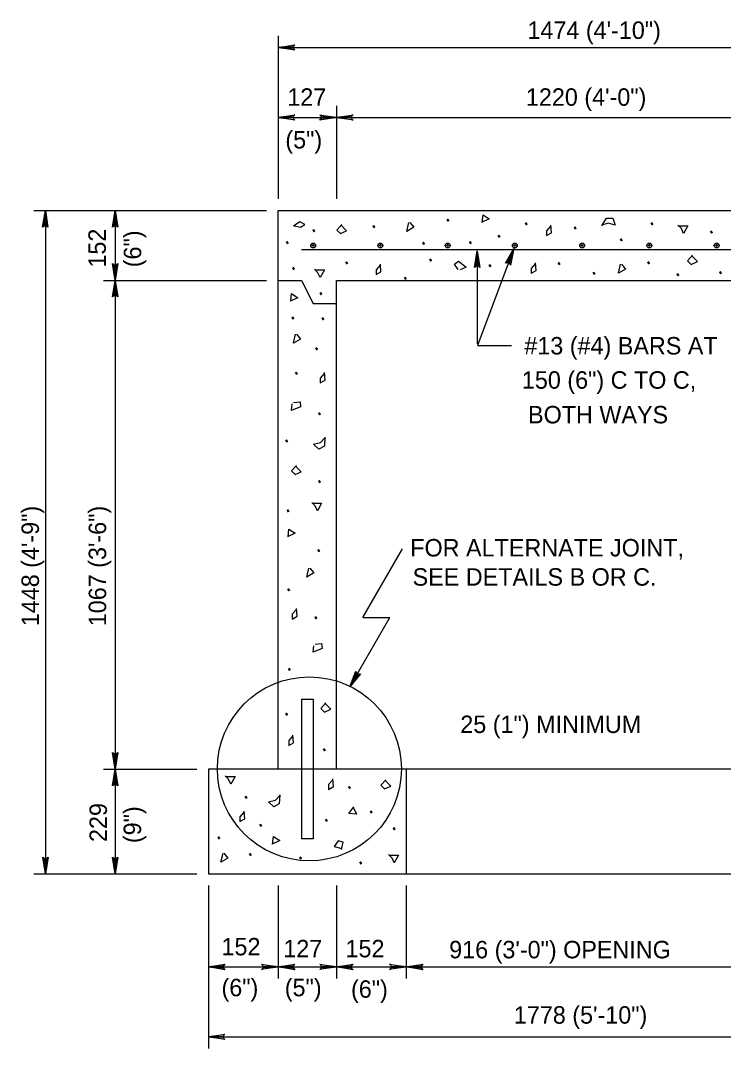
# Model space of a CAD drawing. Extents: x 638443 to 639347, y 298405 to 298999.
# Drawn here: x 638761 to 638881.8, y 298526.6 to 298703.2 of the extents above; entities that cross this region are included whole.
import ezdxf

# ---------------------------------------------------------------- set-up
doc = ezdxf.new("R2010")
doc.units = 0
for name, color, linetype in [('1', 7, 'Continuous'), ('2', 7, 'Continuous'), ('3', 7, 'Continuous')]:
    doc.layers.add(name, color=color, linetype=linetype)

msp = doc.modelspace()

# ---------------------------------------------------------------- linework, layer by layer
at = {"layer": '2'}
for p, q in [((638805.3, 298700.58), (638805.3, 298672.58)), ((638805.3, 298698.58), (638921.3, 298698.58)), ((638815.3, 298688.58), (638815.3, 298672.58)), ((638805.3, 298686.58), (638815.3, 298686.58)), ((638815.3, 298686.58), (638911.3, 298686.58)), ((638763.3, 298670.58), (638803.3, 298670.58)), ((638765.3, 298670.58), (638765.3, 298556.58)), ((638777.3, 298670.58), (638777.3, 298658.58)), ((638805.3, 298574.58), (638805.3, 298670.58)), ((638805.3, 298670.58), (638921.3, 298670.58)), ((638809.33, 298663.89), (638917.33, 298663.89)), ((638839.47, 298663.66), (638839.47, 298647.66)), ((638845.81, 298664.04), (638839.52, 298647.39)), ((638775.3, 298658.58), (638803.3, 298658.58)), ((638777.3, 298658.58), (638777.3, 298574.58)), ((638805.3, 298658.58), (638809.3, 298658.58)), ((638809.3, 298658.58), (638811.3, 298654.58)), ((638815.3, 298574.58), (638815.3, 298658.58)), ((638815.3, 298658.58), (638911.3, 298658.58)), ((638811.3, 298654.58), (638815.3, 298654.58)), ((638839.52, 298647.39), (638845.39, 298647.39)), ((638819.84, 298600.62), (638826.68, 298612.46)), ((638817.62, 298588.73), (638824.48, 298600.62)), ((638819.84, 298600.62), (638824.48, 298600.62)), ((638809.3, 298586.58), (638809.3, 298562.58)), ((638809.3, 298586.58), (638811.3, 298586.58)), ((638811.3, 298586.58), (638811.3, 298562.58)), ((638775.3, 298574.58), (638791.3, 298574.58)), ((638777.3, 298574.58), (638777.3, 298556.58)), ((638933.3, 298574.58), (638793.3, 298574.58)), ((638793.3, 298574.58), (638793.3, 298556.58)), ((638827.3, 298574.58), (638827.3, 298556.58)), ((638811.3, 298562.58), (638809.3, 298562.58)), ((638763.3, 298556.58), (638791.3, 298556.58)), ((638793.3, 298556.58), (638933.3, 298556.58)), ((638793.3, 298554.58), (638793.3, 298526.58)), ((638805.3, 298554.58), (638805.3, 298538.58)), ((638815.3, 298554.58), (638815.3, 298538.58)), ((638827.3, 298554.58), (638827.3, 298538.58)), ((638793.3, 298540.58), (638805.3, 298540.58)), ((638805.3, 298540.58), (638815.3, 298540.58)), ((638815.3, 298540.58), (638827.3, 298540.58)), ((638827.3, 298540.58), (638899.3, 298540.58)), ((638793.3, 298528.58), (638933.3, 298528.58))]:
    msp.add_line(p, q, dxfattribs=at)
for points in [[(638808.02, 298698.24), (638807.92, 298698.44), (638805.3, 298698.58), (638808.02, 298698.24), (638808.16, 298698.12), (638805.3, 298698.58), (638807.92, 298698.71), (638808.01, 298698.91), (638805.3, 298698.58), (638808.16, 298699.04), (638808.01, 298698.91)], [(638808.02, 298686.24), (638807.92, 298686.44), (638805.3, 298686.58), (638808.02, 298686.24), (638808.16, 298686.12), (638805.3, 298686.58), (638807.92, 298686.71), (638808.01, 298686.91), (638805.3, 298686.58), (638808.16, 298687.04), (638808.01, 298686.91)], [(638812.57, 298686.93), (638812.67, 298686.73), (638815.3, 298686.58), (638812.57, 298686.93), (638812.43, 298687.05), (638815.3, 298686.58), (638812.68, 298686.45), (638812.58, 298686.26), (638815.3, 298686.58), (638812.43, 298686.13), (638812.58, 298686.26)], [(638818.02, 298686.24), (638817.92, 298686.44), (638815.3, 298686.58), (638818.02, 298686.24), (638818.16, 298686.12), (638815.3, 298686.58), (638817.92, 298686.71), (638818.01, 298686.91), (638815.3, 298686.58), (638818.16, 298687.04), (638818.01, 298686.91)], [(638764.95, 298667.86), (638765.15, 298667.96), (638765.3, 298670.58), (638764.95, 298667.86), (638764.83, 298667.72), (638765.3, 298670.58), (638765.43, 298667.96), (638765.62, 298667.87), (638765.3, 298670.58), (638765.75, 298667.72), (638765.62, 298667.87)], [(638776.95, 298667.86), (638777.15, 298667.96), (638777.3, 298670.58), (638776.95, 298667.86), (638776.83, 298667.72), (638777.3, 298670.58), (638777.43, 298667.96), (638777.62, 298667.87), (638777.3, 298670.58), (638777.75, 298667.72), (638777.62, 298667.87)], [(638777.64, 298661.31), (638777.44, 298661.21), (638777.3, 298658.58), (638777.64, 298661.31), (638777.76, 298661.45), (638777.3, 298658.58), (638777.17, 298661.2), (638776.97, 298661.3), (638777.3, 298658.58), (638776.84, 298661.45), (638776.97, 298661.3)], [(638776.95, 298655.86), (638777.15, 298655.96), (638777.3, 298658.58), (638776.95, 298655.86), (638776.83, 298655.72), (638777.3, 298658.58), (638777.43, 298655.96), (638777.62, 298655.87), (638777.3, 298658.58), (638777.75, 298655.72), (638777.62, 298655.87)], [(638777.64, 298577.31), (638777.44, 298577.21), (638777.3, 298574.58), (638777.64, 298577.31), (638777.76, 298577.45), (638777.3, 298574.58), (638777.17, 298577.2), (638776.97, 298577.3), (638777.3, 298574.58), (638776.84, 298577.45), (638776.97, 298577.3)], [(638776.95, 298571.86), (638777.15, 298571.96), (638777.3, 298574.58), (638776.95, 298571.86), (638776.83, 298571.72), (638777.3, 298574.58), (638777.43, 298571.96), (638777.62, 298571.87), (638777.3, 298574.58), (638777.75, 298571.72), (638777.62, 298571.87)], [(638765.64, 298559.31), (638765.44, 298559.21), (638765.3, 298556.58), (638765.64, 298559.31), (638765.76, 298559.45), (638765.3, 298556.58), (638765.17, 298559.2), (638764.97, 298559.3), (638765.3, 298556.58), (638764.84, 298559.45), (638764.97, 298559.3)], [(638777.64, 298559.31), (638777.44, 298559.21), (638777.3, 298556.58), (638777.64, 298559.31), (638777.76, 298559.45), (638777.3, 298556.58), (638777.17, 298559.2), (638776.97, 298559.3), (638777.3, 298556.58), (638776.84, 298559.45), (638776.97, 298559.3)], [(638796.02, 298540.24), (638795.92, 298540.44), (638793.3, 298540.58), (638796.02, 298540.24), (638796.16, 298540.12), (638793.3, 298540.58), (638795.92, 298540.71), (638796.01, 298540.91), (638793.3, 298540.58), (638796.16, 298541.04), (638796.01, 298540.91)], [(638802.57, 298540.93), (638802.67, 298540.73), (638805.3, 298540.58), (638802.57, 298540.93), (638802.43, 298541.05), (638805.3, 298540.58), (638802.68, 298540.45), (638802.58, 298540.26), (638805.3, 298540.58), (638802.43, 298540.13), (638802.58, 298540.26)], [(638808.02, 298540.24), (638807.92, 298540.44), (638805.3, 298540.58), (638808.02, 298540.24), (638808.16, 298540.12), (638805.3, 298540.58), (638807.92, 298540.71), (638808.01, 298540.91), (638805.3, 298540.58), (638808.16, 298541.04), (638808.01, 298540.91)], [(638812.57, 298540.93), (638812.67, 298540.73), (638815.3, 298540.58), (638812.57, 298540.93), (638812.43, 298541.05), (638815.3, 298540.58), (638812.68, 298540.45), (638812.58, 298540.26), (638815.3, 298540.58), (638812.43, 298540.13), (638812.58, 298540.26)], [(638818.02, 298540.24), (638817.92, 298540.44), (638815.3, 298540.58), (638818.02, 298540.24), (638818.16, 298540.12), (638815.3, 298540.58), (638817.92, 298540.71), (638818.01, 298540.91), (638815.3, 298540.58), (638818.16, 298541.04), (638818.01, 298540.91)], [(638824.57, 298540.93), (638824.67, 298540.73), (638827.3, 298540.58), (638824.57, 298540.93), (638824.43, 298541.05), (638827.3, 298540.58), (638824.68, 298540.45), (638824.58, 298540.26), (638827.3, 298540.58), (638824.43, 298540.13), (638824.58, 298540.26)], [(638830.02, 298540.24), (638829.92, 298540.44), (638827.3, 298540.58), (638830.02, 298540.24), (638830.16, 298540.12), (638827.3, 298540.58), (638829.92, 298540.71), (638830.01, 298540.91), (638827.3, 298540.58), (638830.16, 298541.04), (638830.01, 298540.91)], [(638796.02, 298528.24), (638795.92, 298528.44), (638793.3, 298528.58), (638796.02, 298528.24), (638796.16, 298528.12), (638793.3, 298528.58), (638795.92, 298528.71), (638796.01, 298528.91), (638793.3, 298528.58), (638796.16, 298529.04), (638796.01, 298528.91)]]:
    msp.add_lwpolyline(points, dxfattribs=at)
at = {"layer": '3'}
for p, q in [((638811.3, 298664.58), (638811.3, 298664.58)), ((638822.85, 298664.58), (638822.85, 298664.58)), ((638834.41, 298664.58), (638834.41, 298664.58)), ((638845.96, 298664.58), (638845.96, 298664.58)), ((638857.52, 298664.58), (638857.52, 298664.58)), ((638869.07, 298664.58), (638869.07, 298664.58)), ((638880.63, 298664.58), (638880.63, 298664.58))]:
    msp.add_line(p, q, dxfattribs=at)
for points in [[(638840.36, 298668.54), (638840.49, 298669.86), (638841.57, 298669.15), (638840.25, 298668.54)], [(638860.9, 298667.97), (638861.73, 298669.28), (638862.81, 298669.28), (638863.18, 298668.08), (638861.97, 298668.43), (638860.9, 298668.08)], [(638808.05, 298667.94), (638809.13, 298667.73), (638809.86, 298668.15), (638809.02, 298668.63), (638807.94, 298667.87)], [(638816.23, 298668.17), (638815.37, 298667.22), (638815.99, 298666.61), (638817.06, 298667.09), (638816.1, 298668.06)], [(638827.89, 298668.54), (638828.62, 298667.71), (638827.41, 298666.98), (638827.76, 298668.54)], [(638852.14, 298667.95), (638851.42, 298667.11), (638851.42, 298666.28), (638852.25, 298666.76), (638852.14, 298668.08)], [(638874.1, 298667.95), (638875.66, 298667.95), (638874.94, 298666.63), (638874.57, 298667.47), (638873.97, 298668.06)], [(638839.13, 298660.94), (638839.33, 298661.04), (638839.47, 298663.66), (638839.13, 298660.94), (638839.01, 298660.8), (638839.47, 298663.66), (638839.6, 298661.04), (638839.8, 298660.94), (638839.47, 298663.66), (638839.93, 298660.8), (638839.8, 298660.94)], [(638844.53, 298661.61), (638844.75, 298661.64), (638845.81, 298664.04), (638844.53, 298661.61), (638844.37, 298661.52), (638845.81, 298664.04), (638845.01, 298661.54), (638845.16, 298661.38), (638845.81, 298664.04), (638845.23, 298661.2), (638845.16, 298661.38)], [(638836.24, 298660.47), (638835.6, 298661.37), (638836.26, 298661.88), (638837.57, 298660.84), (638836.56, 298660.4)], [(638876.5, 298662.88), (638875.64, 298661.94), (638876.26, 298661.33), (638877.33, 298661.81), (638876.37, 298662.77)], [(638811.68, 298660.38), (638813.24, 298660.38), (638812.52, 298659.06), (638812.14, 298659.9), (638811.55, 298660.49)], [(638822.85, 298661.23), (638822.12, 298660.4), (638822.12, 298659.56), (638822.96, 298660.05), (638822.85, 298661.36)], [(638849.49, 298661.47), (638848.76, 298660.64), (638848.76, 298659.8), (638849.6, 298660.29), (638849.49, 298661.6)], [(638864.26, 298661.34), (638864.98, 298660.51), (638863.77, 298659.79), (638864.13, 298661.34)], [(638807.45, 298654.98), (638807.58, 298656.3), (638808.66, 298655.59), (638807.34, 298654.98)], [(638808.43, 298649.34), (638809.16, 298648.5), (638807.95, 298647.78), (638808.3, 298649.34)], [(638813.24, 298642.62), (638812.52, 298641.79), (638812.52, 298640.96), (638813.35, 298641.44), (638813.24, 298642.75)], [(638807.95, 298637.58), (638809.05, 298637.69), (638809.16, 298636.86), (638807.6, 298636.24), (638807.73, 298637.34)], [(638813.29, 298631.66), (638813.23, 298630.11), (638812.3, 298629.57), (638811.37, 298630.43), (638812.59, 298630.72), (638813.35, 298631.57)], [(638808.43, 298626.76), (638807.58, 298625.82), (638808.19, 298625.21), (638809.27, 298625.69), (638808.3, 298626.65)], [(638811.2, 298620.29), (638812.76, 298620.29), (638812.03, 298618.97), (638811.66, 298619.81), (638811.07, 298620.4)], [(638806.99, 298614.52), (638807.12, 298615.84), (638808.19, 298615.13), (638806.88, 298614.52)], [(638810.72, 298609.12), (638811.44, 298608.29), (638810.23, 298607.56), (638810.59, 298609.12)], [(638808.43, 298602.03), (638807.71, 298601.2), (638807.71, 298600.37), (638808.55, 298600.85), (638808.43, 298602.16)], [(638811.66, 298596.04), (638812.76, 298596.15), (638812.87, 298595.32), (638811.31, 298594.71), (638811.44, 298595.8)], [(638819.28, 298590.92), (638819.05, 298590.93), (638817.62, 298588.73), (638819.28, 298590.92), (638819.45, 298590.98), (638817.62, 298588.73), (638818.82, 298591.07), (638818.7, 298591.25), (638817.62, 298588.73), (638818.66, 298591.44), (638818.7, 298591.25)], [(638813.48, 298585.95), (638812.63, 298585.01), (638813.24, 298584.4), (638814.32, 298584.88), (638813.35, 298585.84)], [(638807.84, 298580.31), (638807.12, 298579.48), (638807.12, 298578.64), (638807.95, 298579.12), (638807.84, 298580.44)], [(638796.32, 298573.34), (638797.88, 298573.34), (638797.16, 298572.02), (638796.78, 298572.85), (638796.19, 298573.45)], [(638814.67, 298572.76), (638813.94, 298571.93), (638813.94, 298571.09), (638814.78, 298571.57), (638814.67, 298572.89)], [(638823.79, 298572.74), (638822.94, 298571.8), (638823.55, 298571.19), (638824.63, 298571.67), (638823.66, 298572.63)], [(638805.56, 298570.17), (638805.49, 298568.62), (638804.56, 298568.08), (638803.64, 298568.94), (638804.86, 298569.23), (638805.61, 298570.08)], [(638818.2, 298568.07), (638818.75, 298566.86), (638817.46, 298566.94), (638818.3, 298568.13)], [(638799.44, 298567.23), (638798.71, 298566.4), (638798.71, 298565.56), (638799.55, 298566.05), (638799.44, 298567.36)], [(638804.35, 298561.7), (638804.48, 298563.02), (638805.56, 298562.32), (638804.24, 298561.7)], [(638816.17, 298560.77), (638816.44, 298562.02), (638815.6, 298562.24), (638814.91, 298561.29), (638816.23, 298560.93)], [(638795.95, 298560.15), (638796.67, 298559.31), (638795.47, 298558.59), (638795.82, 298560.15)], [(638824.41, 298559.78), (638825.96, 298559.78), (638825.24, 298558.46), (638824.87, 298559.29), (638824.28, 298559.89)]]:
    msp.add_lwpolyline(points, dxfattribs=at)
for centre, radius in [((638811.3, 298664.58), 0.419), ((638811.3, 298664.58), 0.146), ((638822.85, 298664.58), 0.419), ((638822.85, 298664.58), 0.146), ((638834.41, 298664.58), 0.419), ((638834.41, 298664.58), 0.146), ((638845.96, 298664.58), 0.419), ((638845.96, 298664.58), 0.146), ((638857.52, 298664.58), 0.419), ((638857.52, 298664.58), 0.146), ((638869.07, 298664.58), 0.419), ((638869.07, 298664.58), 0.146), ((638880.63, 298664.58), 0.419), ((638880.63, 298664.58), 0.146), ((638810.66, 298574.63), 15.81)]:
    msp.add_circle(centre, radius, dxfattribs=at)

# ---------------------------------------------------------------- texts
at = {"layer": '1'}
msp.add_text('(5")', height=3, dxfattribs=at).set_placement((638806.53, 298681.24))
at = {"layer": '3'}
for s, p in [('1474 (4\'-10")', (638848.12, 298700.07)), ('127', (638806.87, 298688.58)), ('1220 (4\'-0")', (638847.86, 298688.58)), ('#13 (#4) BARS AT', (638847.59, 298645.84)), ('150 (6") C TO C,', (638847.17, 298639.96)), ('BOTH WAYS', (638848.23, 298634)), ('FOR ALTERNATE JOINT,', (638827.99, 298611.13)), ('SEE DETAILS B OR C.', (638828.39, 298606.11)), ('25 (1") MINIMUM', (638836.59, 298580.79)), ('152', (638795.56, 298542.58)), ('127', (638806.18, 298542.24)), ('152', (638816.87, 298542.24)), ('916 (3\'-0") OPENING', (638834.68, 298542.07)), ('(6")', (638795.56, 298535.55)), ('(5")', (638806.43, 298535.55)), ('(6")', (638817.81, 298535.29)), ('1778 (5\'-10")', (638845.79, 298530.84))]:
    msp.add_text(s, height=3, dxfattribs=at).set_placement(p)
for s, rotation, p in [('.', 210, (638834.83, 298669.39)), ('152', 90, (638775.69, 298660.77)), ('.', 210, (638811.79, 298667.6)), ('.', 210, (638822.11, 298668.3)), ('.', 210, (638848.28, 298668.78)), ('.', 210, (638856.69, 298668.06)), ('.', 210, (638869.89, 298668.78)), ('.', 210, (638880.1, 298667.35)), ('(6")', 90, (638781.77, 298660.83)), ('.', 210, (638807.23, 298665.55)), ('.', 210, (638838.69, 298665.55)), ('.', 210, (638843.61, 298666.63)), ('.', 210, (638864.61, 298666.02)), ('.', 210, (638830.64, 298665.42)), ('.', 210, (638817.43, 298662.07)), ('.', 210, (638831.85, 298662.55)), ('.', 210, (638853.92, 298661.94)), ('.', 210, (638869.3, 298662.07)), ('.', 210, (638808.3, 298661.1)), ('.', 210, (638842.05, 298661.58)), ('.', 210, (638859.93, 298660.27)), ('.', 210, (638881.66, 298660.38)), ('.', 210, (638827.52, 298659.41)), ('.', 210, (638874.33, 298660.03)), ('.', 210, (638813, 298656.78)), ('.', 210, (638808.19, 298652.59)), ('.', 210, (638813.35, 298652.46)), ('.', 210, (638812.27, 298647.3)), ('.', 210, (638808.79, 298643.09)), ('.', 210, (638812.76, 298636.13)), ('.', 210, (638807.12, 298631.46)), ('.', 210, (638812.76, 298624.48)), ('1448 (4\'-9")', 90, (638764.2, 298599.14)), ('1067 (3\'-6")', 90, (638775.74, 298599.14)), ('.', 210, (638807.36, 298619.45)), ('.', 210, (638812.63, 298612.61)), ('.', 210, (638807.47, 298605.88)), ('.', 210, (638812.14, 298601.07)), ('.', 210, (638807.58, 298592.2)), ('.', 210, (638807.12, 298584.5)), ('.', 210, (638813.59, 298578.38)), ('.', 210, (638817.91, 298571.91)), ('.', 210, (638800.14, 298570.22)), ('229', 90, (638775.88, 298562.06)), ('(9")', 90, (638781.74, 298561.87)), ('.', 210, (638821.64, 298567.7)), ('.', 210, (638802.66, 298565.41)), ('.', 210, (638813.94, 298566.27)), ('.', 210, (638825.59, 298564.82)), ('.', 210, (638795.47, 298563.26)), ('.', 210, (638800.87, 298560.39)), ('.', 210, (638809.51, 298559.78)), ('.', 210, (638819.84, 298558.94))]:
    msp.add_text(s, height=3, rotation=rotation, dxfattribs=at).set_placement(p)

doc.saveas('drawing.dxf')
